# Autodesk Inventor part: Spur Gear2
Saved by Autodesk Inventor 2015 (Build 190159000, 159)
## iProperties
Created: 2014-06
Part Number: Spur Gear2
Material: Steel
Document SubType Name: Modeling
Designer: User
Categories: <?xml version="1.0" encoding="UTF-16"?> <MemberInstance><Categories><FamilyTemplate><FamilyTemplateParameter ValueType="xs:double" Id="1" ObjectReferenceKey="da
Density: 1 g/cm^3
Appearance: Steel
CustomPartVersion: 1
Author: User
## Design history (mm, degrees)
sketch "Sketch1"
  geometry: C1 r 8.792 at (0, 0)
  constraints: 1 centre point
  dimensions: "d0" = 17.5849 diameter of C1 (= da_da)
extrude "Extrusion1" new body sketch "Sketch1" distance "d1" = 4 (= da_b); taper "d2" = 0 deg
workplane "Work Plane2"
sketch "Sketch2"
  geometry: C1 r 8.792 at (0, 0) reference; C2 r 8 at (0, 0)
  constraints: 1 centre point, 1 coincident
  dimensions: "d3" = 16 diameter of C2 (= da_dw)
feature "Pitch Diameter" sketch "Sketch2" dims "d4" = 10, "d5" = 0
workplane "Work Plane8"
workplane "Work Plane9"
feature "Spur Gear" dims "da_b" = 4, "da_d" = 15.66489, "da_aw" = 16, "da_da" = 17.5849, "da_df" = 14.0151, "da_dw" = 16, angle "da_beta" = 40 deg, "da_lefttooth" = 0, "da_righttooth" = 10
body "Solid1"
body "Srf1"
other parameters: "d16" = 16 (= da_aw), "d17" = 0, "d34" = 12 deg (computed from da_z), "d39" = 0, "d41" = 0, "d43" = 16 (= da_aw), "d46" = 16 (= da_aw), "d47" = 0, "d48" = 0
